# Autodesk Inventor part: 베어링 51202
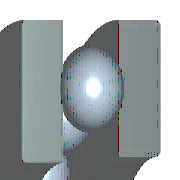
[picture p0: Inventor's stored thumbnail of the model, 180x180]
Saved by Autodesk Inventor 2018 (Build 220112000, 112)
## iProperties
Created: 2012-02
Part Number: 베어링 51202
Material: 강철, 연강
Description: 롤링 베어링 - 플랫 뒷면이 있는 스러스트 볼 베어링
Document SubType Name: Modeling
Standard: KS B 2022
Designer: mduedu
Standards Organization: KS
Language: ko-KR
Size Designation: 51202 - 15 x 32 x 12
Categories: <MemberInstance><Categories><Category DisplayName="샤프트 부품" InternalName="7f7aeb1f-a693-4053-b835-cee3144e0d98" Mnemonic="SHFT"><Category DisplayName="베어링" Inter
Density: 1 g/cm^3
Appearance: 진녹색
IsCustomPart: 1
Author: mduedu
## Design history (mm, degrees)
sketch "스케치1" dims "d3" = 5.28 (= 0.44 x KB)
  geometry: L1 (6, 9.61)-(6, 14.89); L2 (8.64, 12.25)-(3.36, 12.25); L3 (3.6, 16)-(0, 16); L4 (3.6, 7.5)-(0, 7.5); L5 (8.4, 13.35)-(8.4, 16); L6 (8.4, 16)-(12, 16); L7 (12, 16)-(12, 8.5); L8 (12, 8.5)-(8.4, 8.5); L9 (8.4, 8.5)-(8.4, 11.15); L10 (3.6, 16)-(3.6, 13.35); L11 (3.6, 11.15)-(3.6, 7.5); L12 (-1.8, 0)-(10.8, 0) reference; L13 (0, -0.022)-(0, 5.522) reference; 1 further point
  constraints: 22 end point, 5 perpendicular, 2 equal length, 2 midpoint, 2 parallel, 2 point on line, 1 collinear, 10 other
  dimensions: "d8" = 4.8 diameter of L11 L1 (= 0.4 x KB); "d11" = 15 diameter of L4 L12 (= WD); "d12" = 17 diameter of L8 L12 (= KAD1); "d13" = 32 diameter of L3 L12 (= KID1); "d14" = 32 diameter of L6 L12 (= BD); "d15" = 24.5 diameter of point (6, 12.25) L12 (= 0.5 x KID1 + 0.5 x KAD1); "d16" = 6 distance from line of point (6, 12.25) L13 (= 0.5 x KB); "d18" = 12 distance between parallel lines of L7 L13 (= KB)
revolve "본체" stored, may be unused: angle "d9" = 90 deg
revolve "볼" stored, may be unused: angle "d10" = 90 deg
pattern_circular "IDS_ARRAYBALL[SIMPL:T]" dims angle "d2" = 360 deg
body "Solid1"
fillet "모깎기1" dims "d4" = 0.6 (= KRS)
fillet "모깎기2" dims "d5" = 0.6 (= KRS)
other parameters: "WD" = 15 [user parameter; used in 2 equation terms], "KAD1" = 17 [user parameter; used in 3 equation terms], "KID1" = 32 [user parameter; used in 3 equation terms], "BD" = 32 [user parameter; used in 2 equation terms], "KB" = 12 [user parameter; used in 6 equation terms], "KRS" = 0.6 [user parameter; used in 2 equation terms], "d0" = 2.4 (= 0.2 x KB), "d6" = 0, "d7" = 0, "d19" = 0, "d41" = 0, "d42" = 0, "WR" = 7.5 (= 0.5 x WD) [user parameter], "BC" = 1.65e+07 [user parameter], "BBA" = 90 deg [user parameter], "BC0" = 2.7e+07 [user parameter], "BR" = 16 (= 0.5 x BD) [user parameter]
